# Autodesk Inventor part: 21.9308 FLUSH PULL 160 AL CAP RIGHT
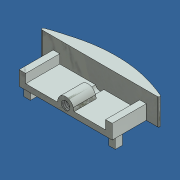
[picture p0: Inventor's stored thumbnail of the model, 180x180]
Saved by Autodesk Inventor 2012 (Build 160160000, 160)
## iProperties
Created: 2014-08
Part Number: 21.9308 FLUSH PULL 160 AL CAP RIGHT
Material: Steel
Document SubType Name: Modeling
Designer: Admin
Density: 7.85 g/cm^3
Mass: 24.219 g
Surface Area: 26.6596 cm^2
Volume: 3.08522 cm^3
Author: Admin
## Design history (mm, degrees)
sketch "Sketch1"
  geometry: L1 (20.883, 6.377)-(16.633, 6.377) reference; L2 (-18.867, 6.377)-(-23.117, 6.377) reference; L3 (-18.867, -2.323)-(-18.867, 6.377) reference; L4 (-18.867, -6.623)-(-18.867, -5.123) reference; L5 (16.633, -6.623)-(-18.867, -6.623) reference; L6 (16.633, -5.123)-(16.633, -6.623) reference; L7 (16.633, 6.377)-(16.633, -2.323) reference; L8 (16.633, -2.323)-(16.633, -5.123); L9 (-18.867, -5.123)-(-18.867, -2.323); L10 (-18.79, 8.817)-(-14.633, 9.993); A1 r 0.5 centre (20.883, 6.877) between (20.883, 6.377) and (21.081, 7.336) reference; A2 r 60.225 centre (-2.715, -47.988) between (21.081, 7.336) and (7.565, 11.353) reference; A3 r 59.036 centre (-2.715, -47.988) between (-18.79, 8.817) and (-23.291, 7.346) reference; A4 r 0.5 centre (-23.117, 6.877) between (-23.291, 7.346) and (-23.117, 6.377) reference; A5 r 52.216 centre (-0.415, -40.25) between (21.081, 7.336) and (-14.633, 9.993); A6 r 1.59 centre (-18.357, 7.287) between (-16.767, 7.287) and (-18.79, 8.817) reference; 2 further points
  constraints: 6 end point, 4 point on circle, 2 tangent, 1 centre point, 1 collinear, 1 parallel
extrude "Extrusion1" new body sketch "Sketch1" distance "d0" = 5.5; taper "d1" = 0 deg
sketch "Sketch2"
  geometry: L1 (20.883, 6.377)-(16.633, 6.377) reference; L2 (-18.79, 8.817)-(-14.633, 9.993) reference; L3 (-18.867, 6.377)-(-23.117, 6.377) reference; L4 (16.633, 6.377)-(16.633, -6.623) reference; L5 (-18.867, 6.377)-(16.633, 6.377); A1 r 0.5 centre (20.883, 6.877) between (20.883, 6.377) and (21.081, 7.336) reference; A2 r 60.225 centre (-2.715, -47.988) between (21.081, 7.336) and (7.565, 11.353) reference; A3 r 52.216 centre (-0.415, -40.25) between (7.565, 11.353) and (-14.633, 9.993) reference; A4 r 59.036 centre (-2.715, -47.988) between (-18.79, 8.817) and (-23.291, 7.346) reference; A5 r 0.5 centre (-23.117, 6.877) between (-23.291, 7.346) and (-23.117, 6.377) reference; 1 further point
  constraints: 2 end point, 1 perpendicular
extrude "Extrusion2" join sketch "Sketch2" distance "d2" = 4.5; taper "d3" = 0 deg
sketch "Sketch3"
  geometry: L1 (35.5, 5.5)-(0, 5.5) reference; L2 (0, 0)-(0, 5.5) reference; L3 (0, 0)-(35.5, 0) reference; L4 (35.5, 0)-(35.5, 5.5) reference; L5 (2.5, 5.5)-(33, 5.5); L6 (33, 5.5)-(33, 2.1); L7 (33, 2.1)-(2.5, 2.1); L8 (2.5, 2.1)-(2.5, 5.5); 1 further point
  constraints: 8 end point, 2 parallel, 1 horizontal, 1 perpendicular, 1 point on line
  dimensions: "d4" = 2.5 distance between parallel lines of L6 L4; "d5" = 2.5 distance between parallel lines of L8 L2; "d6" = 2.1 distance between parallel lines of L7 L3
extrude "Extrusion3" cut sketch "Sketch3" distance "d7" = 13; taper "d8" = 0 deg
sketch "Sketch4"
  geometry: L1 (0, 0)-(0, 5.5) reference; L2 (0, 0)-(35.5, 0) reference; L3 (35.5, 0)-(35.5, 5.5) reference; L4 (33, 2.1)-(2.5, 2.1) reference; L5 (14.852, 3.276)-(14.537, 2.1); L6 (20.648, 3.276)-(20.963, 2.1); A1 r 3 centre (17.75, 2.5) between (20.648, 3.276) and (14.852, 3.276); 1 further point
  constraints: 4 end point, 2 point on circle, 2 point on line, 2 tangent, 1 centre point
  dimensions: "d9" = 35.5 distance between parallel lines of L3 L1 (derived); "d10" = 17.75 distance from line of A1.centre L1 (= 0.5 x d9); "d11" = 5.5 dimension on A1 L2; "d12" = 2.5 distance from line of A1.centre L2; "d13" = 75 deg angle of L5 L4; "d14" = 75 deg angle of L6 L4
extrude "Extrusion4" join sketch "Sketch4" distance "d15" = 8.5; taper "d16" = 0 deg
sketch "Sketch5"
  geometry: A1 r 3 centre (17.75, 2.5) between (20.648, 3.276) and (14.852, 3.276) reference; 2 further points
  constraints: 1 coincident
hole "Hole1" sketch "Sketch5" at (17.75, 2.5) diameter "d17" = 3.242; stored, may be unused: countersink angle "d21" = 90 deg, drill point angle "d23" = 0 deg; dims "d18" = 9, "d19" = 4, "d20" = 2, "d22" = 13
sketch "Sketch6"
  geometry: L1 (-16.633, -6.623)-(-16.633, 6.377) reference; L2 (18.867, 6.377)-(18.867, -6.623) reference; L3 (16.067, -2.323)-(18.867, -2.323) reference; L4 (16.067, -5.123)-(16.067, -2.323) reference; L5 (18.867, -5.123)-(16.067, -5.123) reference; L6 (-16.633, -2.323)-(-13.833, -2.323) reference; L7 (-13.833, -2.323)-(-13.833, -5.123) reference; L8 (-13.833, -5.123)-(-16.633, -5.123) reference; L9 (-16.333, -2.323)-(-16.333, -5.123); L10 (18.567, -2.323)-(18.567, -5.123); 1 further point
  constraints: 4 end point, 4 point on line, 2 perpendicular
  dimensions: "d24" = 0.3 distance between parallel lines of L9 L1; "d25" = 0.3 distance between parallel lines of L10 L2
extrude "Extrusion5" join sketch "Sketch6" distance "d26" = 4; taper "d27" = 0 deg
body "Solid1"
node "Reference1"
node "Reference2"
node "Reference3"
node "Reference5"
node "Reference6"
node "Reference7"
node "Reference8"
node "Reference9"
node "Reference10"
node "Reference11"
node "Reference12"
node "Reference13"
node "Reference14"
node "Reference15"
node "Reference16"
node "Reference17"
node "Reference18"
node "Reference19"
